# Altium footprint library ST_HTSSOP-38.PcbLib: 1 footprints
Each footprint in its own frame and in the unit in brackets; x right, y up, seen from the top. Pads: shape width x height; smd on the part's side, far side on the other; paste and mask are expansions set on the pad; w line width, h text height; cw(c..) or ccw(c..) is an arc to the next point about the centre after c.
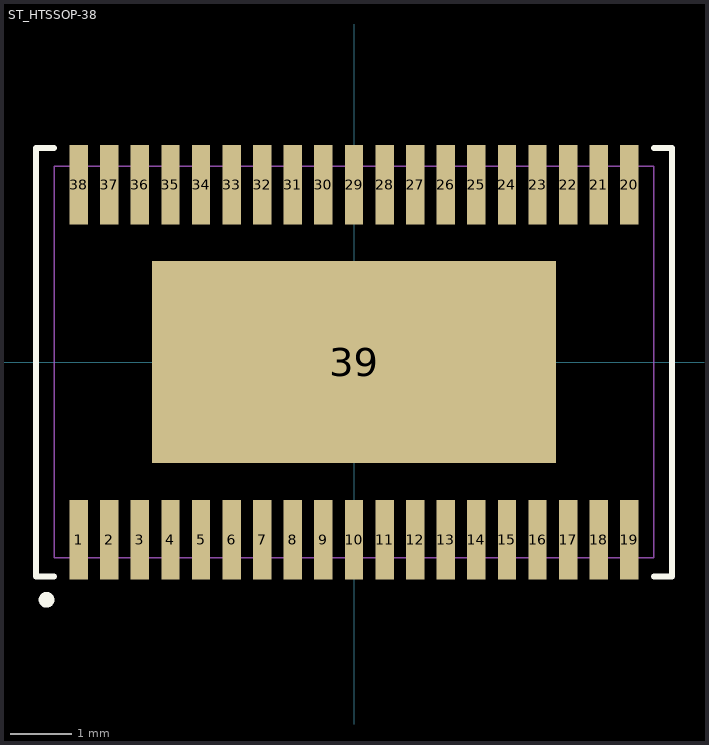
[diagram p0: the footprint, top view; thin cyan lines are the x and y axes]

## ST_HTSSOP-38 [mm] "ST_HTSSOP-38"
pads (39):
  rect 0.3x1.3 smd mask+0.025: 1(-4.5,-2.9) 2(-4,-2.9) 3(-3.5,-2.9) 4(-3,-2.9) 5(-2.5,-2.9) 6(-2,-2.9) 7(-1.5,-2.9) 8(-1,-2.9) 9(-0.5,-2.9) 10(0,-2.9) 11(0.5,-2.9) 12(1,-2.9) 13(1.5,-2.9) 14(2,-2.9) 15(2.5,-2.9) 16(3,-2.9) 17(3.5,-2.9) 18(4,-2.9) 19(4.5,-2.9) 20(4.5,2.9) 21(4,2.9) 22(3.5,2.9) 23(3,2.9) 24(2.5,2.9) 25(2,2.9) 26(1.5,2.9) 27(1,2.9) 28(0.5,2.9) 29(0,2.9) 30(-0.5,2.9) 31(-1,2.9) 32(-1.5,2.9) 33(-2,2.9) 34(-2.5,2.9) 35(-3,2.9) 36(-3.5,2.9) 37(-4,2.9) 38(-4.5,2.9)
  rect 6.6x3.3 smd mask+0.05: 39(0,0)
Top Overlay:
  circle w0.15: c-5.025,-3.885 r0.053
  lines w0.1: -4.9,-3.5 -5.2,-3.5 -5.2,3.5 -4.9,3.5 ; 4.9,-3.5 5.2,-3.5 5.2,3.5 4.9,3.5
Mechanical 5:
  text "38" at -4.59,3.7 h0.2
  text "6" at -2.13,-4 h0.2
  text "5" at -2.63,-4 h0.2
  text "39" at -1.59,0 h0.2
  text "3" at -3.63,-4 h0.2
  text "34" at -2.59,3.7 h0.2
  text "29" at -0.12,3.7 h0.2
  text "2" at -4.13,-4 h0.2
  text "37" at -4.09,3.7 h0.2
  text "36" at -3.59,3.7 h0.2
  text "28" at 0.41,3.7 h0.2
  text "19" at 4.41,-4 h0.2
  text "18" at 3.91,-4 h0.2
  text "33" at -2.09,3.7 h0.2
  text "31" at -1.09,3.7 h0.2
  text "20" at 4.41,3.7 h0.2
  text "21" at 3.91,3.7 h0.2
  text "22" at 3.41,3.7 h0.2
  text "23" at 2.91,3.7 h0.2
  text "24" at 2.41,3.7 h0.2
  text "25" at 1.91,3.7 h0.2
  text "26" at 1.41,3.7 h0.2
  text "27" at 0.91,3.7 h0.2
  text "16" at 2.91,-4 h0.2
  text "15" at 2.41,-4 h0.2
  text "14" at 1.91,-4 h0.2
  text "13" at 1.41,-4 h0.2
  text "11" at 0.41,-4 h0.2
  text "10" at -0.22,-4 h0.2
  text "9" at -0.63,-4 h0.2
  text "8" at -1.13,-4 h0.2
  text "1" at -4.63,-4 h0.2
  text "30" at -0.59,3.7 h0.2
  text "17" at 3.41,-4 h0.2
  text "12" at 0.91,-4 h0.2
  text "7" at -1.63,-4 h0.2
  text "4" at -3.13,-4 h0.2
  text "32" at -1.59,3.7 h0.2
  text "35" at -3.09,3.7 h0.2
Mechanical 6:
  lines w0.025: -4.9,-3.2 -4.9,3.2 4.9,3.2 4.9,-3.2 -4.9,-3.2
Assembly:
  lines w0.025: -4.9,-3.2 4.9,-3.2 4.9,3.2 -4.9,3.2 -4.9,-3.2
3D body: height 1.1, standoff 0.05, extent -4.9,-3.2 4.9,3.2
